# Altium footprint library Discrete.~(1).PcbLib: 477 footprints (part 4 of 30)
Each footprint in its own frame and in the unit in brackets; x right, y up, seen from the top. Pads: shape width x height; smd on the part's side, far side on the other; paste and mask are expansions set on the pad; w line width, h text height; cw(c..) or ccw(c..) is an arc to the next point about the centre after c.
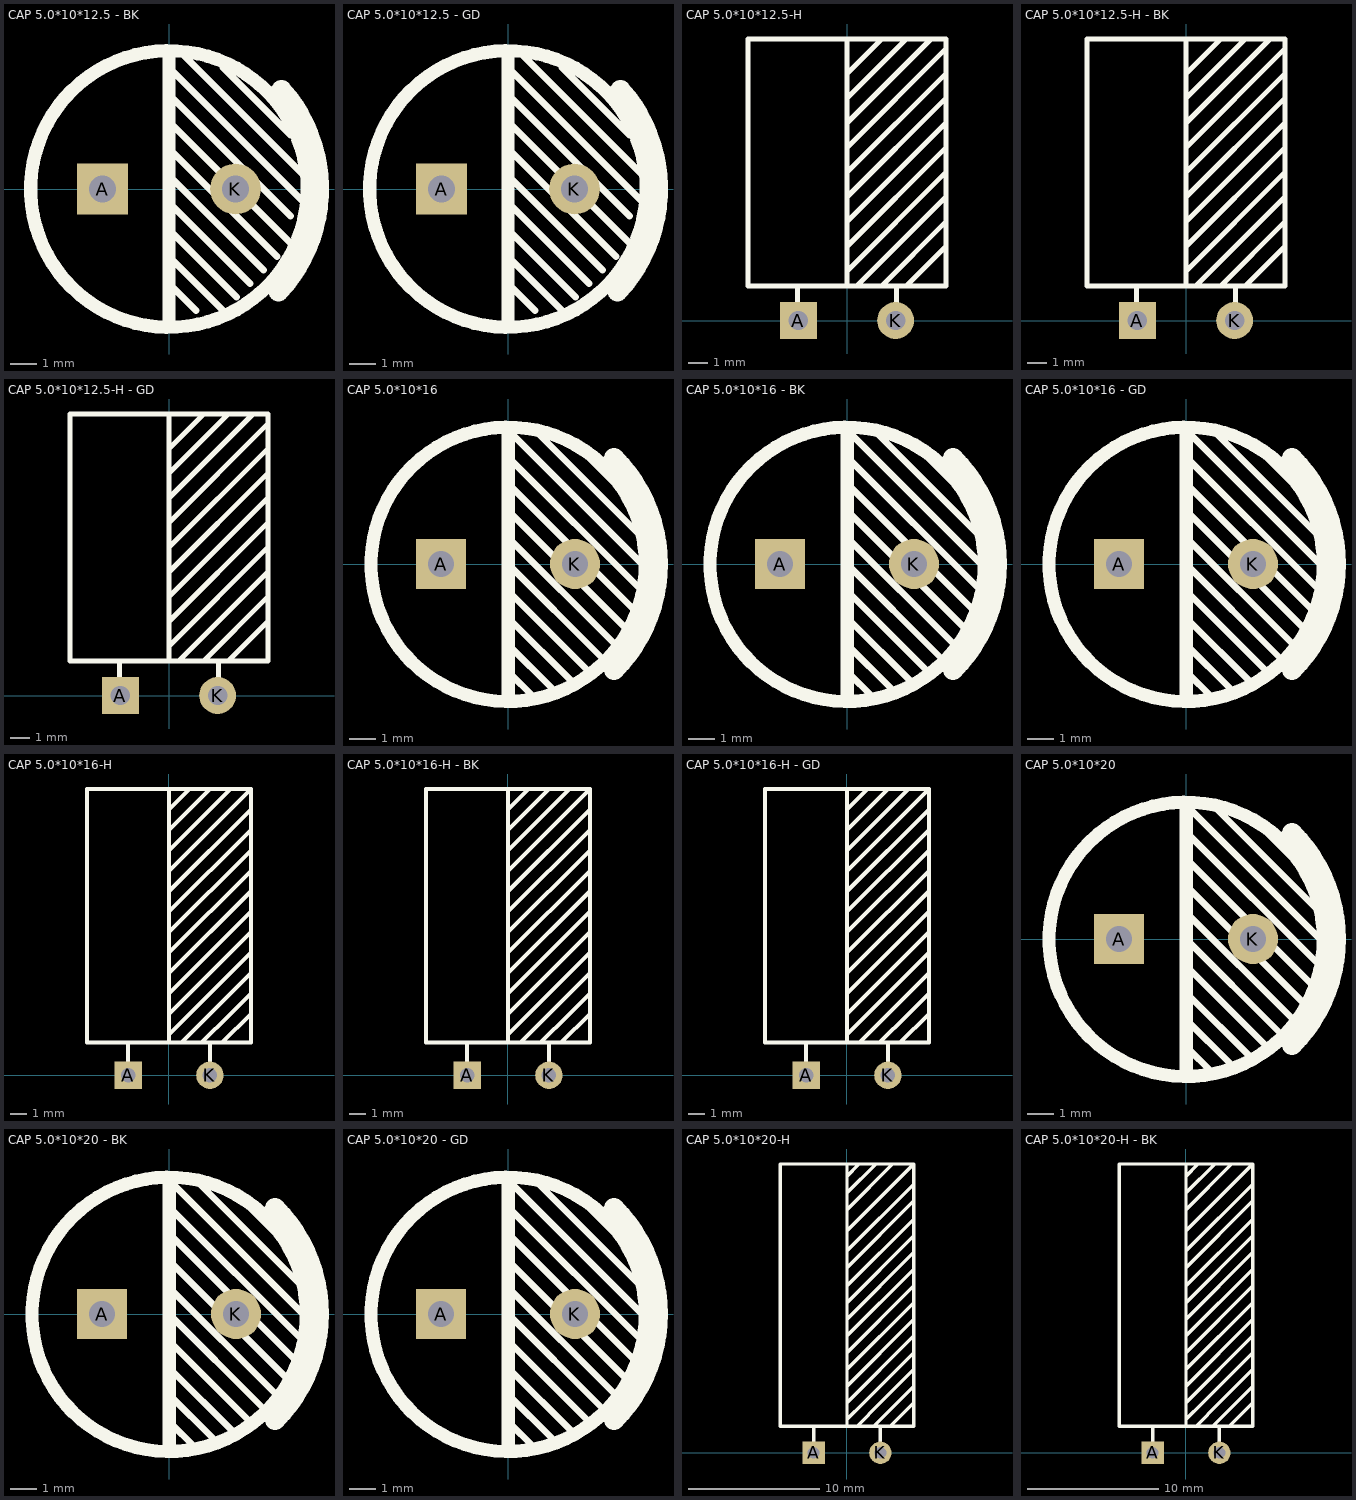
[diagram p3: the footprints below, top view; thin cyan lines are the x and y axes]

## CAP 5.0*10*12.5 - BK [mm] "脚距5mm直径10mm高度12.5mm"
pads (2):
  rect 1.9x1.9 hole 1: A(-2.5,0)
  round 1.9 hole 1: K(2.5,0)
Top Overlay:
  circle w0.5: c0,0 r5.2
  lines w0.254: 0,-3.556 1.016,-4.572 ; 0,-2.54 2.032,-4.572 ; 0,-1.524 2.54,-4.064 ; 0,-1.016 0,-0.508 3.048,-3.556 ; 0,0.508 3.556,-3.048 ; 0,1.524 4.064,-2.54 ; 0,2.54 4.572,-2.032 ; 0,3.556 4.572,-1.016 ; 0,4.572 5.08,-0.508 ; 0.508,5.08 5.08,0.508 ; 2.032,4.572 4.572,2.032
  lines w0.5: 0,-5 0,5
  lines w0.75: 4.114,-3.857 ccw(c0,0) 4.229,3.731
3D body "CAP 5X10X12.5.STEP": height 12.54, standoff -3.37, extent -5,-4.999 5.01,4.999

## CAP 5.0*10*12.5 - GD [mm] "脚距5mm直径10mm高度12.5mm"
pads (2):
  rect 1.9x1.9 hole 1: A(-2.5,0)
  round 1.9 hole 1: K(2.5,0)
Top Overlay:
  circle w0.5: c0,0 r5.2
  lines w0.254: 0,-3.556 1.016,-4.572 ; 0,-2.54 2.032,-4.572 ; 0,-1.524 2.54,-4.064 ; 0,-1.016 0,-0.508 3.048,-3.556 ; 0,0.508 3.556,-3.048 ; 0,1.524 4.064,-2.54 ; 0,2.54 4.572,-2.032 ; 0,3.556 4.572,-1.016 ; 0,4.572 5.08,-0.508 ; 0.508,5.08 5.08,0.508 ; 2.032,4.572 4.572,2.032
  lines w0.5: 0,-5 0,5
  lines w0.75: 4.114,-3.857 ccw(c0,0) 4.229,3.731
3D body "CAP 5X10X12.5.STEP": height 12.54, standoff -3.37, extent -5,-4.999 5.01,4.999

## CAP 5.0*10*12.5-H [mm] "脚距5mm直径10mm高度12.5mm"
pads (2):
  rect 1.9x1.9 hole 1: A(-2.5,0)
  round 1.9 hole 1: K(2.5,0)
Top Overlay:
  lines w0.254: -2.54,0.762 -2.54,1.778 ; 0,1.778 0,14.41 ; 0,2.54 5.08,7.62 ; 0,3.81 5.08,8.89 ; 0,5.08 5.08,10.16 ; 0,6.35 5.08,11.43 ; 0,7.62 5.08,12.7 ; 0,8.89 5.08,13.97 ; 0,10.16 4.318,14.478 ; 0,11.43 3.048,14.478 ; 0,12.7 1.778,14.478 ; 0.508,1.778 5.08,6.35 ; 1.778,1.778 5.08,5.08 ; 2.54,0.762 2.54,1.778 ; 3.048,1.778 5.08,3.81 ; -5.08,1.778 -5.08,14.478 5.08,14.478 5.08,1.778 -5.08,1.778
3D body "CAP 5X10X12.5-H.STEP": height 10.03, standoff -3.47, extent -5,-0.3 5.01,14.41

## CAP 5.0*10*12.5-H - BK [mm] "脚距5mm直径10mm高度12.5mm"
pads (2):
  rect 1.9x1.9 hole 1: A(-2.5,0)
  round 1.9 hole 1: K(2.5,0)
Top Overlay:
  lines w0.254: -2.54,0.762 -2.54,1.778 ; 0,1.778 0,14.41 ; 0,2.54 5.08,7.62 ; 0,3.81 5.08,8.89 ; 0,5.08 5.08,10.16 ; 0,6.35 5.08,11.43 ; 0,7.62 5.08,12.7 ; 0,8.89 5.08,13.97 ; 0,10.16 4.318,14.478 ; 0,11.43 3.048,14.478 ; 0,12.7 1.778,14.478 ; 0.508,1.778 5.08,6.35 ; 1.778,1.778 5.08,5.08 ; 2.54,0.762 2.54,1.778 ; 3.048,1.778 5.08,3.81 ; -5.08,1.778 -5.08,14.478 5.08,14.478 5.08,1.778 -5.08,1.778
3D body "CAP 5X10X12.5-H.STEP": height 10.03, standoff -3.48, extent -5,-0.3 5.01,14.41

## CAP 5.0*10*12.5-H - GD [mm] "脚距5mm直径10mm高度12.5mm"
pads (2):
  rect 1.9x1.9 hole 1: A(-2.5,0)
  round 1.9 hole 1: K(2.5,0)
Top Overlay:
  lines w0.254: -2.54,0.762 -2.54,1.778 ; 0,1.778 0,14.478 ; 0,2.54 5.08,7.62 ; 0,3.81 5.08,8.89 ; 0,5.08 5.08,10.16 ; 0,6.35 5.08,11.43 ; 0,7.62 5.08,12.7 ; 0,8.89 5.08,13.97 ; 0,10.16 4.318,14.478 ; 0,11.43 3.048,14.478 ; 0,12.7 1.778,14.478 ; 0.508,1.778 5.08,6.35 ; 1.778,1.778 5.08,5.08 ; 2.54,0.762 2.54,1.778 ; 3.048,1.778 5.08,3.81 ; -5.08,1.778 5.08,1.778 5.08,14.478 -5.08,14.478 -5.08,1.778
3D body "CAP 5X10X12.5-H.STEP": height 10.03, standoff -3.48, extent -5,-0.3 5.01,14.41

## CAP 5.0*10*16 [mm] "脚距5mm直径10mm高度16mm"
pads (2):
  rect 1.9x1.9 hole 1: A(-2.54,0)
  round 1.9 hole 1: K(2.54,0)
Top Overlay:
  circle w0.5: c0.006,-0.013 r5.2
  lines w0.254: 0,-1.016 3.048,-4.064 ; 0,0 3.556,-3.556 ; 0,2.032 4.572,-2.54 ; 0,3.048 4.826,-1.778 4.953,-1.778 ; 0.006,-5.082 0.006,-5.075 ; 0.006,-4.064 0.006,-4.07 1.016,-5.08 ; 0.006,-3.043 0.006,-3.05 0.006,-3.054 1.714,-4.763 ; 0.006,-2.032 0.006,-2.038 2.54,-4.572 ; 0.006,1.016 0.006,1.01 4.064,-3.048 ; 0.006,4.064 0.006,4.058 5.08,-1.016 ; 0.006,5.187 0.006,5.074 5.08,0 ; 1.016,5.08 5.08,1.016 ; 2.54,4.572 4.572,2.54
  lines w0.5: 0.006,-5.197 0.006,5.072
  lines w0.75: 4.021,-4.021 ccw(c0,0) 4.021,4.021
3D body "CAP 5X10X16.STEP": height 16.04, standoff -3.37, extent -5,-5 5.01,5

## CAP 5.0*10*16 - BK [mm] "脚距5mm直径10mm高度16mm"
pads (2):
  rect 1.9x1.9 hole 1: A(-2.54,0)
  round 1.9 hole 1: K(2.54,0)
Top Overlay:
  circle w0.5: c0.006,-0.013 r5.2
  lines w0.254: 0,-1.016 3.048,-4.064 ; 0,0 3.556,-3.556 ; 0,2.032 4.572,-2.54 ; 0,3.048 4.826,-1.778 4.953,-1.778 ; 0.006,-5.082 0.006,-5.075 ; 0.006,-4.064 0.006,-4.07 1.016,-5.08 ; 0.006,-3.043 0.006,-3.05 0.006,-3.054 1.714,-4.763 ; 0.006,-2.032 0.006,-2.038 2.54,-4.572 ; 0.006,1.016 0.006,1.01 4.064,-3.048 ; 0.006,4.064 0.006,4.058 5.08,-1.016 ; 0.006,5.187 0.006,5.074 5.08,0 ; 1.016,5.08 5.08,1.016 ; 2.54,4.572 4.572,2.54
  lines w0.5: 0.006,-5.197 0.006,5.072
  lines w0.75: 4.021,-4.021 ccw(c0,0) 4.021,4.021
3D body "CAP 5X10X16.STEP": height 16.04, standoff -3.37, extent -5,-5 5.01,5

## CAP 5.0*10*16 - GD [mm] "脚距5mm直径10mm高度16mm"
pads (2):
  rect 1.9x1.9 hole 1: A(-2.54,0)
  round 1.9 hole 1: K(2.54,0)
Top Overlay:
  circle w0.5: c0.006,-0.013 r5.2
  lines w0.254: 0,-1.016 3.048,-4.064 ; 0,0 3.556,-3.556 ; 0,2.032 4.572,-2.54 ; 0,3.048 4.826,-1.778 4.953,-1.778 ; 0.006,-5.082 0.006,-5.075 ; 0.006,-4.064 0.006,-4.07 1.016,-5.08 ; 0.006,-3.043 0.006,-3.05 0.006,-3.054 1.714,-4.763 ; 0.006,-2.032 0.006,-2.038 2.54,-4.572 ; 0.006,1.016 0.006,1.01 4.064,-3.048 ; 0.006,4.064 0.006,4.058 5.08,-1.016 ; 0.006,5.187 0.006,5.074 5.08,0 ; 1.016,5.08 5.08,1.016 ; 2.54,4.572 4.572,2.54
  lines w0.5: 0.006,-5.197 0.006,5.072
  lines w0.75: 4.021,-4.021 ccw(c0,0) 4.021,4.021
3D body "CAP 5X10X16.STEP": height 16.04, standoff -3.37, extent -5,-5 5.01,5

## CAP 5.0*10*16-H [mm] "脚距5mm直径10mm高度16mm"
pads (2):
  rect 1.7x1.7 hole 0.9: A(-2.54,0)
  round 1.7 hole 0.9: K(2.54,0)
Top Overlay:
  lines w0.254: -2.54,0.762 -2.54,1.778 -2.54,2.032 ; 0,2.032 0,2.54 ; 0,4.064 0,2.54 ; 0,5.08 5.08,10.16 ; 0,6.35 5.08,11.43 ; 0,7.62 5.08,12.7 ; 0,8.89 5.08,13.97 ; 0,10.16 5.08,15.24 ; 0,11.43 5.08,16.51 ; 0,12.7 5.08,17.78 ; 0,13.97 3.81,17.78 ; 0,15.24 2.54,17.78 ; 0,16.51 1.27,17.78 ; 0,17.78 0,3.81 5.08,8.89 ; 0.762,2.032 2.54,3.81 5.08,6.35 ; 2.032,2.032 3.81,3.81 5.08,5.08 ; 2.54,0.762 2.54,1.778 2.54,2.032 ; 3.302,2.032 5.08,3.81 ; 5.08,7.62 1.27,3.81 0,2.54 ; 5.08,17.78 5.08,2.032 -5.08,2.032 -5.08,17.78 5.08,17.78
3D body "CAP 5X10X16-H.STEP": height 10.03, standoff -3.47, extent -5.04,-0.3 4.97,17.91

## CAP 5.0*10*16-H - BK [mm] "脚距5mm直径10mm高度16mm"
pads (2):
  rect 1.7x1.7 hole 0.9: A(-2.54,0)
  round 1.7 hole 0.9: K(2.54,0)
Top Overlay:
  lines w0.254: -2.54,0.762 -2.54,1.778 -2.54,2.032 ; 0,2.032 0,2.54 ; 0,4.064 0,2.54 ; 0,5.08 5.08,10.16 ; 0,6.35 5.08,11.43 ; 0,7.62 5.08,12.7 ; 0,8.89 5.08,13.97 ; 0,10.16 5.08,15.24 ; 0,11.43 5.08,16.51 ; 0,12.7 5.08,17.78 ; 0,13.97 3.81,17.78 ; 0,15.24 2.54,17.78 ; 0,16.51 1.27,17.78 ; 0,17.78 0,3.81 5.08,8.89 ; 0.762,2.032 2.54,3.81 5.08,6.35 ; 2.032,2.032 3.81,3.81 5.08,5.08 ; 2.54,0.762 2.54,1.778 2.54,2.032 ; 3.302,2.032 5.08,3.81 ; 5.08,7.62 1.27,3.81 0,2.54 ; 5.08,17.78 5.08,2.032 -5.08,2.032 -5.08,17.78 5.08,17.78
3D body "CAP 5X10X16-H.STEP": height 10.03, standoff -3.48, extent -5.04,-0.3 4.97,17.91

## CAP 5.0*10*16-H - GD [mm] "脚距5mm直径10mm高度16mm"
pads (2):
  rect 1.7x1.7 hole 0.9: A(-2.54,0)
  round 1.7 hole 0.9: K(2.54,0)
Top Overlay:
  lines w0.254: -2.54,0.762 -2.54,1.778 -2.54,2.032 ; 0,2.032 0,2.54 ; 0,4.064 0,2.54 ; 0,5.08 5.08,10.16 ; 0,6.35 5.08,11.43 ; 0,7.62 5.08,12.7 ; 0,8.89 5.08,13.97 ; 0,10.16 5.08,15.24 ; 0,11.43 5.08,16.51 ; 0,12.7 5.08,17.78 ; 0,13.97 3.81,17.78 ; 0,15.24 2.54,17.78 ; 0,16.51 1.27,17.78 ; 0,17.78 0,3.81 5.08,8.89 ; 0.762,2.032 2.54,3.81 5.08,6.35 ; 2.032,2.032 3.81,3.81 5.08,5.08 ; 2.54,0.762 2.54,1.778 2.54,2.032 ; 3.302,2.032 5.08,3.81 ; 5.08,7.62 1.27,3.81 0,2.54 ; 5.08,17.78 -5.08,17.78 -5.08,2.032 5.08,2.032 5.08,17.78
3D body "CAP 5X10X16-H.STEP": height 10.03, standoff -3.48, extent -5.04,-0.3 4.97,17.91

## CAP 5.0*10*20 [mm] "脚距5mm直径10mm高度20mm"
pads (2):
  rect 1.9x1.9 hole 1: A(-2.54,0)
  round 1.9 hole 1: K(2.54,0)
Top Overlay:
  circle w0.5: c0.006,-0.013 r5.2
  lines w0.254: 0,-1.016 3.048,-4.064 ; 0,0 3.556,-3.556 ; 0,2.032 4.572,-2.54 ; 0,3.048 4.826,-1.778 4.953,-1.778 ; 0.006,-5.082 0.006,-5.075 ; 0.006,-4.064 0.006,-4.07 1.016,-5.08 ; 0.006,-3.043 0.006,-3.05 0.006,-3.054 1.714,-4.763 ; 0.006,-2.032 0.006,-2.038 2.54,-4.572 ; 0.006,1.016 0.006,1.01 4.064,-3.048 ; 0.006,4.064 0.006,4.058 5.08,-1.016 ; 0.006,5.187 0.006,5.074 5.08,0 ; 1.016,5.08 5.08,1.016 ; 2.54,4.572 4.572,2.54
  lines w0.5: 0.006,-5.197 0.006,5.072
  lines w0.75: 4.021,-4.021 ccw(c0,0) 4.021,4.021
3D body "CAP 5X10X20.STEP": height 20.03, standoff -3.38, extent -5,-4.998 5.01,4.998

## CAP 5.0*10*20 - BK [mm] "脚距5mm直径10mm高度20mm"
pads (2):
  rect 1.9x1.9 hole 1: A(-2.54,0)
  round 1.9 hole 1: K(2.54,0)
Top Overlay:
  circle w0.5: c0.006,-0.013 r5.2
  lines w0.254: 0,-1.016 3.048,-4.064 ; 0,0 3.556,-3.556 ; 0,2.032 4.572,-2.54 ; 0,3.048 4.826,-1.778 4.953,-1.778 ; 0.006,-5.082 0.006,-5.075 ; 0.006,-4.064 0.006,-4.07 1.016,-5.08 ; 0.006,-3.043 0.006,-3.05 0.006,-3.054 1.714,-4.763 ; 0.006,-2.032 0.006,-2.038 2.54,-4.572 ; 0.006,1.016 0.006,1.01 4.064,-3.048 ; 0.006,4.064 0.006,4.058 5.08,-1.016 ; 0.006,5.187 0.006,5.074 5.08,0 ; 1.016,5.08 5.08,1.016 ; 2.54,4.572 4.572,2.54
  lines w0.5: 0.006,-5.197 0.006,5.072
  lines w0.75: 4.021,-4.021 ccw(c0,0) 4.021,4.021
3D body "CAP 5X10X20.STEP": height 20.04, standoff -3.37, extent -5,-4.998 5.01,4.998

## CAP 5.0*10*20 - GD [mm] "脚距5mm直径10mm高度20mm"
pads (2):
  rect 1.9x1.9 hole 1: A(-2.54,0)
  round 1.9 hole 1: K(2.54,0)
Top Overlay:
  circle w0.5: c0.006,-0.013 r5.2
  lines w0.254: 0,-1.016 3.048,-4.064 ; 0,0 3.556,-3.556 ; 0,2.032 4.572,-2.54 ; 0,3.048 4.826,-1.778 4.953,-1.778 ; 0.006,-5.082 0.006,-5.075 ; 0.006,-4.064 0.006,-4.07 1.016,-5.08 ; 0.006,-3.043 0.006,-3.05 0.006,-3.054 1.714,-4.763 ; 0.006,-2.032 0.006,-2.038 2.54,-4.572 ; 0.006,1.016 0.006,1.01 4.064,-3.048 ; 0.006,4.064 0.006,4.058 5.08,-1.016 ; 0.006,5.187 0.006,5.074 5.08,0 ; 1.016,5.08 5.08,1.016 ; 2.54,4.572 4.572,2.54
  lines w0.5: 0.006,-5.197 0.006,5.072
  lines w0.75: 4.021,-4.021 ccw(c0,0) 4.021,4.021
3D body "CAP 5X10X20.STEP": height 20.04, standoff -3.37, extent -5,-4.998 5.01,4.998

## CAP 5.0*10*20-H [mm] "脚距5mm直径10mm高度20mm"
pads (2):
  rect 1.7x1.7 hole 0.9: A(-2.54,0)
  round 1.7 hole 0.9: K(2.54,0)
Top Overlay:
  lines w0.254: -2.54,0.762 -2.54,1.778 -2.54,2.032 ; 0,2.032 0,2.54 ; 0,4.064 0,2.54 ; 0,5.08 5.08,10.16 ; 0,6.35 5.08,11.43 ; 0,7.62 5.08,12.7 ; 0,8.89 5.08,13.97 ; 0,10.16 5.08,15.24 ; 0,11.43 5.08,16.51 ; 0,12.7 5.08,17.78 ; 0,14.097 5.08,19.177 ; 0,15.367 5.08,20.447 ; 0,16.891 5.08,21.971 ; 0,18.5 3.45,21.95 ; 0,19.77 2.18,21.95 ; 0,21.04 0.91,21.95 ; 0,21.971 0,3.81 5.08,8.89 ; 0.762,2.032 2.54,3.81 5.08,6.35 ; 2.032,2.032 3.81,3.81 5.08,5.08 ; 2.54,0.762 2.54,1.778 2.54,2.032 ; 3.302,2.032 5.08,3.81 ; 5.08,7.62 1.27,3.81 0,2.54 ; 5.08,21.971 5.08,2.032 -5.08,2.032 -5.08,21.971 5.08,21.971
3D body "CAP 5X10X20-H.STEP": height 10.03, standoff -3.47, extent -5.04,-0.3 4.97,21.91

## CAP 5.0*10*20-H - BK [mm] "脚距5mm直径10mm高度20mm"
pads (2):
  rect 1.7x1.7 hole 0.9: A(-2.54,0)
  round 1.7 hole 0.9: K(2.54,0)
Top Overlay:
  lines w0.254: -2.54,0.762 -2.54,1.778 -2.54,2.032 ; 0,2.032 0,2.54 ; 0,4.064 0,2.54 ; 0,5.08 5.08,10.16 ; 0,6.35 5.08,11.43 ; 0,7.62 5.08,12.7 ; 0,8.89 5.08,13.97 ; 0,10.16 5.08,15.24 ; 0,11.43 5.08,16.51 ; 0,12.7 5.08,17.78 ; 0,14.097 5.08,19.177 ; 0,15.367 5.08,20.447 ; 0,16.891 5.08,21.971 ; 0,18.5 3.45,21.95 ; 0,19.77 2.18,21.95 ; 0,21.04 0.91,21.95 ; 0,21.971 0,3.81 5.08,8.89 ; 0.762,2.032 2.54,3.81 5.08,6.35 ; 2.032,2.032 3.81,3.81 5.08,5.08 ; 2.54,0.762 2.54,1.778 2.54,2.032 ; 3.302,2.032 5.08,3.81 ; 5.08,7.62 1.27,3.81 0,2.54 ; 5.08,21.971 5.08,2.032 -5.08,2.032 -5.08,21.971 5.08,21.971
3D body "CAP 5X10X20-H.STEP": height 10.03, standoff -3.48, extent -5.04,-0.3 4.97,21.91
